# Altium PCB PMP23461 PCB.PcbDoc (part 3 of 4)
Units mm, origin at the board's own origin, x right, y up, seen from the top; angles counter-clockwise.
Board outline 240.04 x 159.92 mm, 6 copper layers (Layer 1, Layer 2, Layer 3, Layer 4, Layer 5, Layer 6), stack 2.017 mm thick; 241 components, 120 nets, 654 pads, 744 vias.
Unrouted connection lines stored in the file: 3.
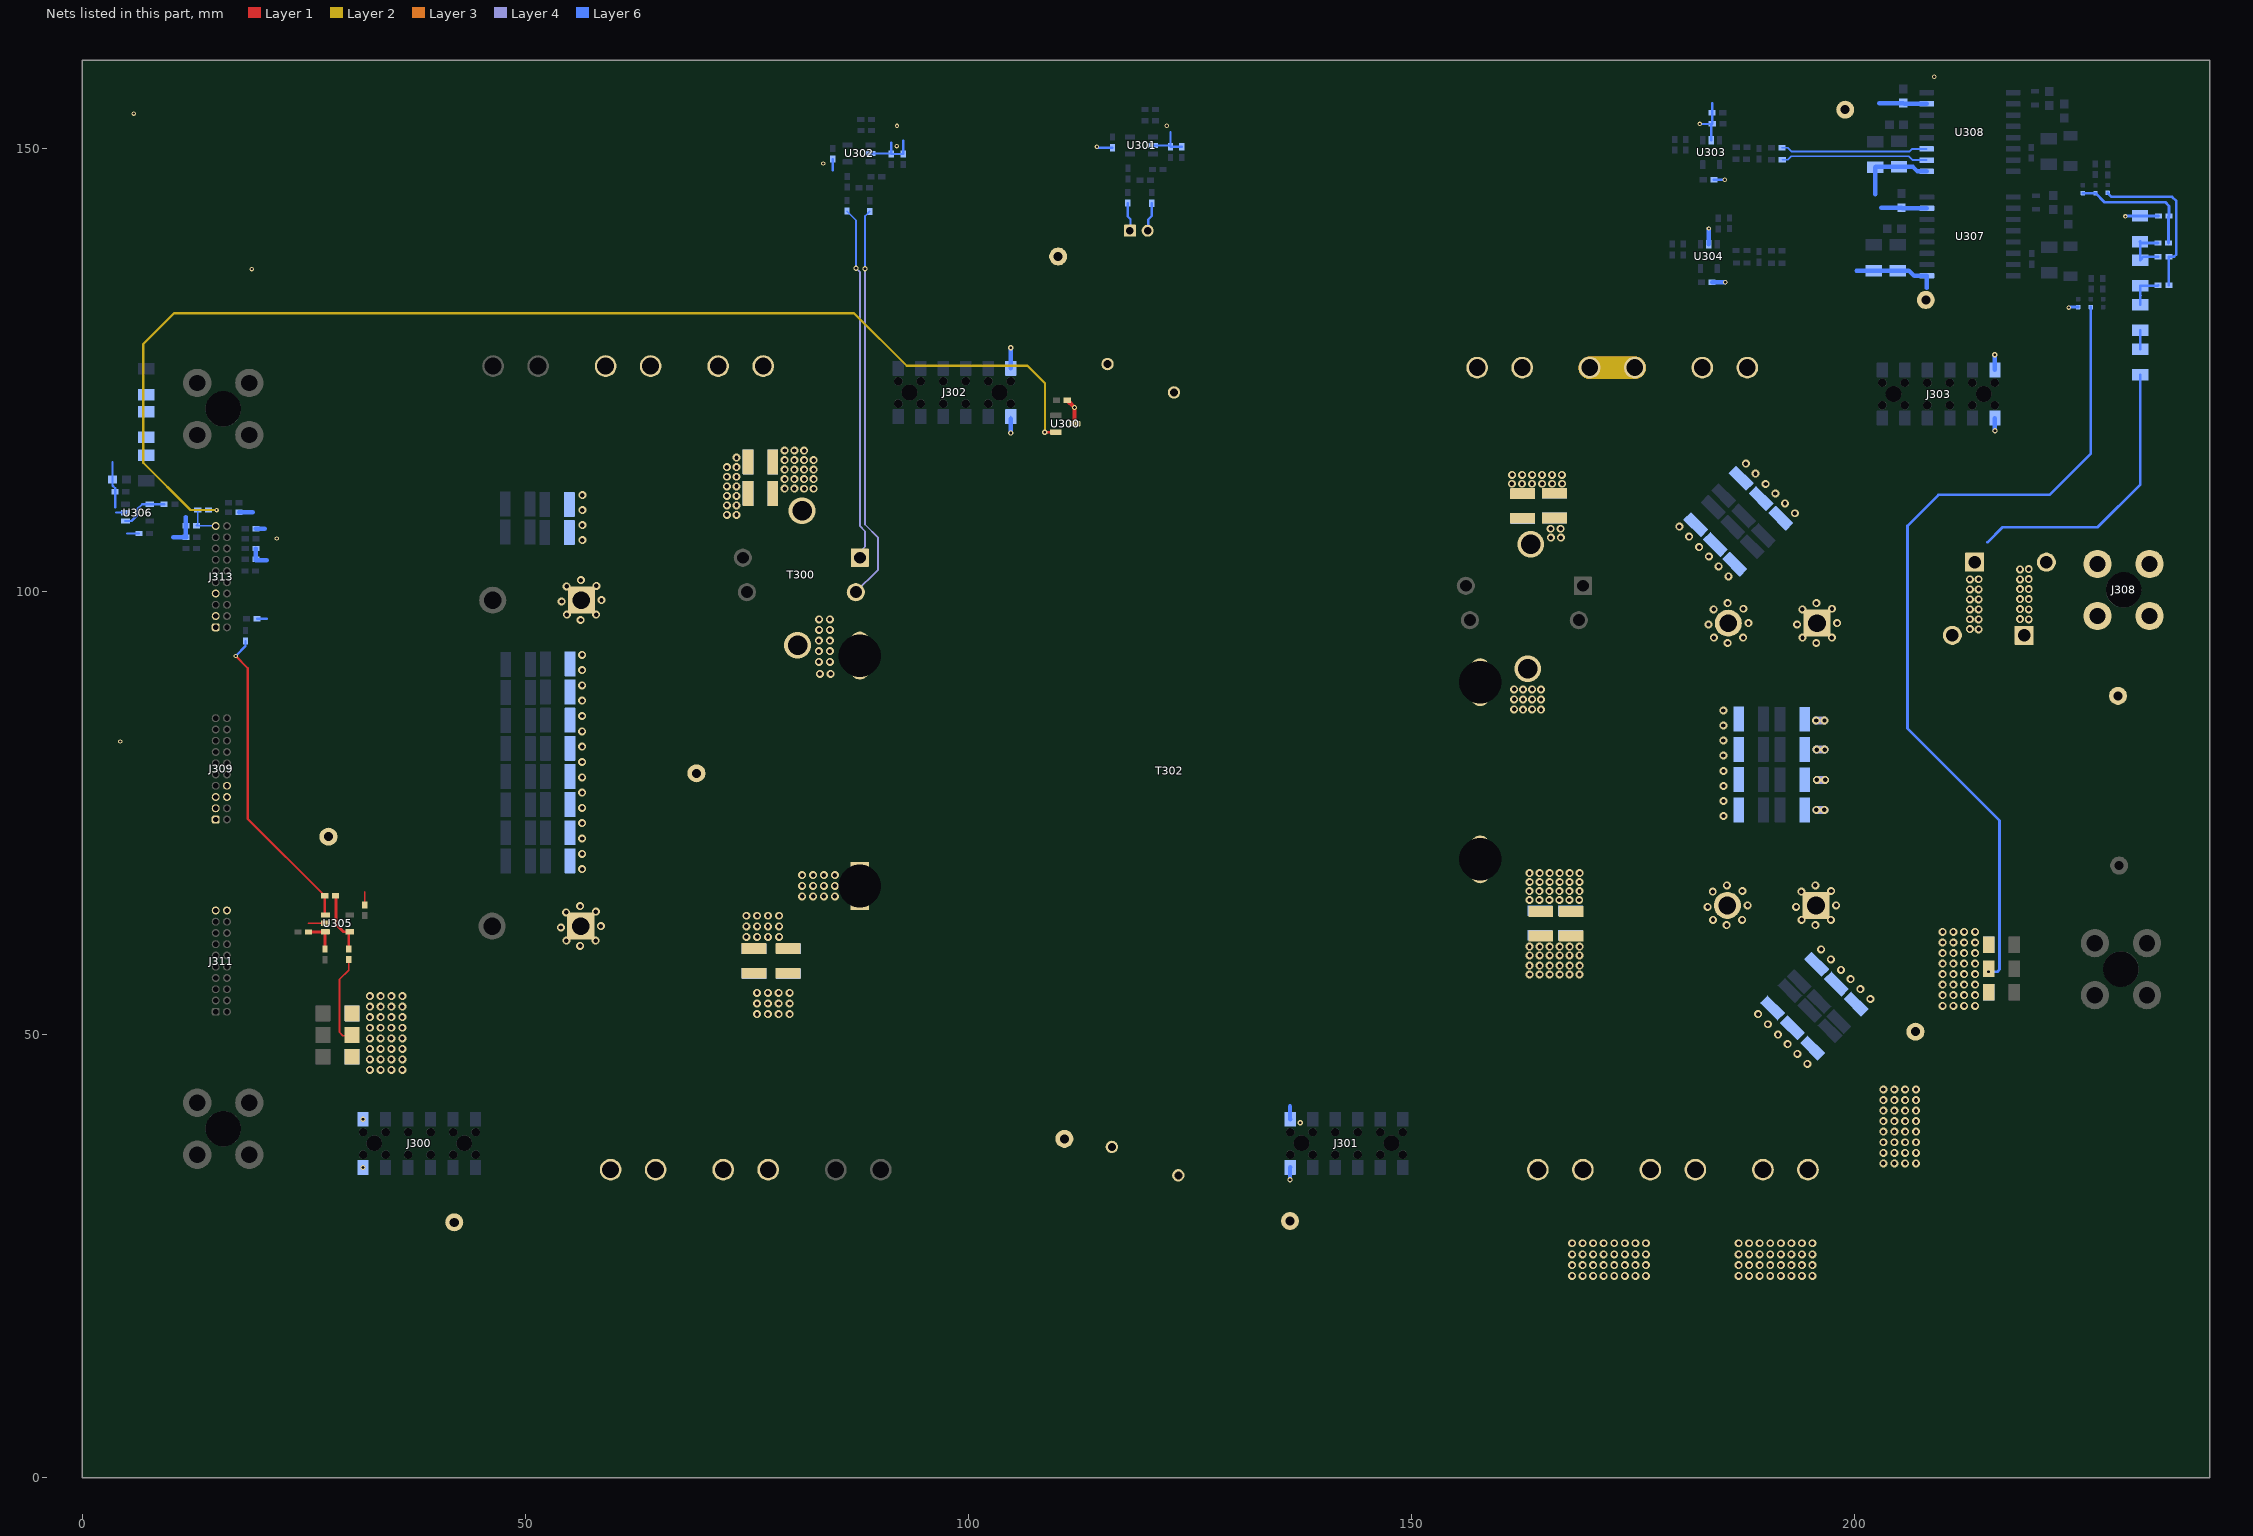
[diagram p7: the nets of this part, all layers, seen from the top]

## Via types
v1: diameter 0.9, hole 0.5, Layer 1 to Layer 6, 634 vias
v2: diameter 0.6, hole 0.3, Layer 1 to Layer 6, 52 vias
v3: diameter 0.5, hole 0.25, Layer 1 to Layer 6, 42 vias
v4: diameter 4, hole 4, Layer 1 to Layer 6, 12 vias
v5: diameter 3, hole 2.2, Layer 1 to Layer 6, 4 vias

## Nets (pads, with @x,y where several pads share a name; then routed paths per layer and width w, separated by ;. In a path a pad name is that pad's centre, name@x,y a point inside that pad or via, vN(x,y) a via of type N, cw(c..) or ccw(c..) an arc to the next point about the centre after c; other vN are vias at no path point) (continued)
NetR307_1: R307.1 U300.2 | length 138.1
  Layer 1 w0.254: v2(108.61,117.949) 108.622,117.961 U300.2@109.853,117.961
  Layer 2 w0.254: v3(15.137,109.177) 12.209,109.177 6.857,114.529 6.857,127.914 10.337,131.394 87.07,131.394 93.014,125.451 106.654,125.451 108.61,123.495 v2(108.61,117.949)
  Layer 6 w0.254: R307.1@14.213,109.195 14.231,109.177 v3(15.137,109.177)
NetR333_1: R333.1 R335.1 R340.1 R345.1 | length 6.4
  Layer 6 w0.305: R333.1@232.192,139.468 R333.1@232.224,139.437 ; R333.1@232.224,139.517 R333.1@232.224,139.437 ; R335.1@234.212,139.316 232.344,139.316 R333.1@232.224,139.437 ; R340.1@234.238,137.767 232.602,137.767 R345.1@232.224,137.388 R333.1@232.224,139.437
NetR336_2: R336.2 R356.1 U305.4 | length 7.1
  Layer 1 w0.305: R356.1@28.548,65.644 28.625,65.568 28.625,62.433 29.468,61.59 U305.4@30.168,61.59 30.056,61.479 R336.2@30.056,59.666
NetR342_2: R342.2 R348.1 U305.3 | length 3.8
  Layer 1 w0.305: R342.2@25.516,61.57 27.363,61.57 27.38,61.552 R348.1@27.38,59.63
NetR345_2: R345.2 R349.1 R351.1 | length 4.2
  Layer 6 w0.305: R351.1@232.224,132.359 232.224,133.374 ; 232.247,133.398 232.224,133.374 ; R349.1@234.238,134.541 234.185,134.488 R345.2@232.224,134.488 232.224,133.374
NetR346_1: R346.1 R356.2 U305.1 | length 35.5
  Layer 1 w0.254: v3(17.296,92.71) 18.668,91.338 18.668,74.324 R356.2@27.348,65.644 27.348,63.559 U305.1@27.418,63.49
  Layer 6 w0.254: v3(17.296,92.71) 18.414,93.828 R346.1@18.414,94.38
NetR347_1: R347.1 U306.1 U306.4 | length 5.6
  Layer 6 w0.254: U306.1@4.848,107.94 5.551,107.94 6.172,108.561 6.172,109.245 6.767,109.84 U306.4@7.598,109.84 9.22,109.84 R347.1@9.23,109.83
NetR350_1: R350.1 R352.2
NetR351_2: R351.2 R353.1 | length 2.1
  Layer 6 w0.305: R353.1@232.224,127.33 R351.2@232.224,129.459
NetR352_1: R352.1 R355.2
PGND: C300.2 C301.2 C318.2 C319.1 C320.1 C322.2 C324.2 C326.2 C327.2 C328.2 C330.2 C332.2 C333.2 C334.1 C335.2 C338.2 C339.2 C342.2 C344.2 C345.2 C346.2 C348.2 C349.2 C350.2 C354.2 C355.2 C357.2 C363.2 C364.2 C366.2 C369.2 C370.2 C371.2 C372.2 C373.2 C374.2 C375.2 C376.2 J300.11 J300.12 J301.11 J301.12 J302.11 J302.12 J303.11 J303.12 J309.1 J309.3 J309.5 J309.6 J309.8 J311.19 J311.20 J313.1 J313.3 R300.2 R302.2 R304.2 R306.2 R309.2 R311.1 R318.1 R319.1 R336.1 R339.2 TP300.1 TP302.1 TP312.1 TP314.1 TP327.1 TP328.1 TP329.1 TP330.1 TP331.1 TP332.1 TP333.1 TP334.1 U300.3 U301.2 U302.2 U303.2 U304.2 U305.2 U306.2 U307.9 U307.15 U308.9 U308.15 | length 97.9
  Layer 1 w0.2: 25.496,62.54 U305.2@27.418,62.54 ; R336.1@30.056,58.466 30.056,57.261 29.006,56.21 29.006,50.241 29.387,49.86 30.365,49.86 R304.2@30.443,49.938 ; C349.2@31.851,64.633 31.851,66.091
  Layer 1 w0.5: C322.2@111.13,121.578 v2(111.953,120.756) U300.3@111.953,118.911
  Layer 6 w0.2: J302.11@104.764,119.482 J302.11@104.764,119.73
  Layer 6 w0.254: 3.391,114.567 R339.2@3.391,112.624 3.391,111.951 3.693,111.649 C345.2@3.693,111.227 3.693,109.498 ; 3.785,108.89 U306.2@4.848,108.89 ; 5.055,106.528 C350.2@6.368,106.528 ; C344.2@19.716,96.926 20.799,96.926 ; 84.668,147.482 C338.2@84.668,148.8 ; U302.2@88.945,149.421 91.221,149.421 C335.2@91.277,149.366 ; 91.277,150.658 C335.2@91.277,149.366 ; 92.623,150.879 R319.1@92.623,149.361 92.618,149.366 C335.2@91.277,149.366 ; v3(114.477,150.165) 114.574,150.067 C330.2@116.236,150.067 ; U301.2@120.817,150.317 122.642,150.317 C327.2@122.789,150.17 ; 122.789,151.841 C327.2@122.789,150.17 ; R311.1@124.059,150.17 C327.2@122.789,150.17 ; v3(182.513,152.756) C334.1@183.889,152.756 ; U303.2@183.794,150.905 C334.1@183.794,152.66 ; 183.905,155.083 R318.1@183.905,154 183.905,152.772 C334.1@183.889,152.756 ; C334.1@183.921,152.756 C334.1@183.889,152.756 ; C339.2@184.099,146.457 v3(185.319,146.457)
  Layer 6 w0.5: 10.261,106.096 C328.2@11.702,106.096 ; 11.667,106.416 C318.2@11.667,107.417 11.667,108.391 ; C342.2@17.668,108.949 19.228,108.949 ; C332.2@19.573,104.838 19.573,103.53 19.547,103.505 20.802,103.505 ; C346.2@19.573,107.086 20.584,107.086 ; v2(104.764,117.881) J302.11@104.764,119.482 ; J302.12@104.764,125.17 104.774,125.18 v2(104.774,127.508) ; v2(136.27,33.604) 136.27,34.973 J301.12@136.293,34.996 ; 136.27,41.885 136.27,40.459 J301.11@136.293,40.436 ; U304.2@183.538,139.167 v3(183.538,140.947) ; C348.2@183.901,134.896 v3(185.392,134.896) ; 200.198,136.19 C354.2@202.148,136.19 202.162,136.204 C355.2@204.864,136.204 206.098,136.204 206.694,135.608 U307.9@208.144,135.608 208.144,134.239 ; 202.3,144.816 C363.2@202.3,147.848 202.352,147.9 C364.2@204.991,147.9 206.569,147.9 207.075,147.393 U308.9@208.119,147.393 ; 202.758,155.102 C366.2@205.475,155.102 205.564,155.013 U308.15@208.119,155.013 ; 203.011,143.292 C357.2@205.271,143.292 205.335,143.228 U307.15@208.144,143.228 ; v2(215.797,126.705) 215.813,126.689 J303.12@215.813,124.993 ; J303.11@215.813,119.553 215.813,118.12 v2(215.823,118.11)
  other v1: 32.43,45.999 33.65,45.999 34.869,45.999 36.113,45.999 32.43,47.19 33.65,47.19 34.869,47.19 36.113,47.19 32.43,48.38 33.65,48.38 34.869,48.38 36.113,48.38 32.43,49.57 33.65,49.57 34.869,49.57 36.113,49.57 32.43,50.76 33.65,50.76 34.869,50.76 36.113,50.76 32.43,51.95 33.65,51.95 34.869,51.95 36.113,51.95 32.43,53.14 33.65,53.14 34.869,53.14 36.113,53.14 32.43,54.331 33.65,54.331 34.869,54.331 36.113,54.331 56.161,59.992 54.612,60.601 57.914,60.601 54.002,62.075 58.512,62.227 54.586,63.776 57.939,63.853 56.169,64.488 56.387,68.656 56.387,70.384 56.387,72.112 56.387,73.84 56.387,75.568 56.387,77.296 56.387,79.024 56.387,80.752 56.387,82.48 56.387,84.207 56.387,85.935 56.387,87.663 56.387,89.391 56.387,91.119 56.387,92.847 56.228,96.774 54.679,97.384 57.981,97.384 54.069,98.857 58.579,99.009 54.653,100.559 58.006,100.635 56.236,101.27 56.412,105.791 56.412,107.484 56.412,109.178 56.412,110.871
  other v2: 31.671,34.996 137.414,40.056 31.671,40.436
  other v3: 4.266,83.058 21.919,105.969 19.1,136.373 83.591,148.285 91.896,150.254 91.923,152.527 122.351,152.552 5.79,153.918 208.966,158.064
ROG_PRI_N: R322.1 T300.2 | length 45
  Layer 4 w0.2: T300.2@87.173,99.835 89.788,102.45 89.788,106.07 88.313,107.546 v2(88.313,136.423)
  Layer 6 w0.2: v2(88.313,136.423) 88.313,142.352 R322.1@88.838,142.878
ROG_PRI_P: R327.1 T300.1 | length 40.3
  Layer 4 w0.203: v2(87.299,136.449) 87.756,135.992 87.756,107.35 88.313,106.793 88.313,105.029 87.63,104.346 T300.1@87.63,103.721
  Layer 6 w0.203: R327.1@86.281,142.906 87.299,141.887 v2(87.299,136.449)
ROG_SEC_N: J304.2 R312.1 | length 3
  Layer 6 w0.254: J304.2@120.272,140.941 120.272,141.959 120.681,142.367 R312.1@120.681,143.796
ROG_SEC_P: J304.1 R314.1 | length 3
  Layer 6 w0.254: R314.1@117.963,143.807 117.963,142.313 118.272,142.003 J304.1@118.272,140.941
SGND: C300.1 C301.1 C323.1 C325.1 C377.2 C378.2 C379.2 C380.2 C381.2 C382.2 C383.2 C384.2 C385.2 C386.2 FB300.1 FB301.1 R301.1 R303.1 R305.1 R308.1 R310.1 R332.1 R333.2 TP301.1 TP303.1 TP313.1 TP315.1 TP324.1 | length 104.8
  Layer 4 w0.9: v1(195.642,85.432) v1@196.531,85.432 ; v1(195.655,75.345) v1(196.57,75.345) ; v1(195.696,82.144) v1(196.61,82.144) ; v1(195.731,78.74) v1(196.646,78.74)
  Layer 6 w0.305: v2(215.086,57.074) 216.077,57.074 216.331,57.328 216.331,74.143 205.943,84.53 205.943,107.391 209.448,110.896 221.996,110.896 226.618,115.518 226.618,132.069 FB301.1@226.633,132.084 ; v3(224.154,132.029) 224.209,132.084 FB300.1@225.211,132.084 ; v3(230.545,142.313) 230.6,142.368 R333.2@232.192,142.368 232.196,142.364 R332.1@234.263,142.364
  other v1: 168.097,22.758 169.287,22.758 170.478,22.758 171.668,22.758 172.858,22.758 174.048,22.758 175.238,22.758 176.428,22.758 186.893,22.758 188.083,22.758 189.274,22.758 190.464,22.758 191.654,22.758 192.844,22.758 194.034,22.758 195.224,22.758 168.097,23.978 169.287,23.978 170.478,23.978 171.668,23.978 172.858,23.978 174.048,23.978 175.238,23.978 176.428,23.978 186.893,23.978 188.083,23.978 189.274,23.978 190.464,23.978 191.654,23.978 192.844,23.978 194.034,23.978 195.224,23.978 168.097,25.197 169.287,25.197 170.478,25.197 171.668,25.197 172.858,25.197 174.048,25.197 175.238,25.197 176.428,25.197 186.893,25.197 188.083,25.197 189.274,25.197 190.464,25.197 191.654,25.197 192.844,25.197 194.034,25.197 195.224,25.197 168.097,26.441 169.287,26.441 170.478,26.441 171.668,26.441 172.858,26.441 174.048,26.441 175.238,26.441 176.428,26.441 186.893,26.441 188.083,26.441 189.274,26.441 190.464,26.441 191.654,26.441 192.844,26.441 194.034,26.441 195.224,26.441 203.225,35.458 204.47,35.458 205.689,35.458 206.908,35.458 203.225,36.649 204.47,36.649 205.689,36.649 206.908,36.649 203.225,37.839 204.47,37.839 205.689,37.839 206.908,37.839 203.225,39.029 204.47,39.029 205.689,39.029 206.908,39.029 203.225,40.219 204.47,40.219 205.689,40.219 206.908,40.219 203.225,41.409 204.47,41.409 205.689,41.409 206.908,41.409 203.225,42.599 204.47,42.599 205.689,42.599 206.908,42.599 203.225,43.79 204.47,43.79 205.689,43.79 206.908,43.79 209.905,53.238 211.124,53.238 212.343,53.238 213.588,53.238 201.751,54.006 209.905,54.429 211.124,54.429 212.343,54.429 213.588,54.429 200.634,55.118 209.905,55.619 211.124,55.619 212.343,55.619 213.588,55.619 199.541,56.236 209.905,56.809 211.124,56.809 212.343,56.809 213.588,56.809 198.449,57.302 209.905,57.999 211.124,57.999 212.343,57.999 213.588,57.999 197.306,58.471 209.905,59.189 211.124,59.189 212.343,59.189 213.588,59.189 196.214,59.614 209.905,60.379 211.124,60.379 212.343,60.379 213.588,60.379 209.905,61.57 211.124,61.57 212.343,61.57 213.588,61.57 195.549,62.329 193.999,62.938 197.301,62.938 193.39,64.411 197.9,64.564 193.974,66.113 197.327,66.189 195.557,66.824 196.581,85.432 195.654,94.18 194.105,94.79 197.407,94.79 193.495,96.263 198.005,96.415 194.079,97.965 197.432,98.041 195.662,98.676 193.242,108.819 192.125,109.931 191.032,111.049 189.94,112.116 188.797,113.284 187.705,114.427
SW_A: C310.2 C312.2 C314.2 C316.2 TP316.1 TP318.1
  other v1: 72.719,108.636 73.811,108.636 72.719,109.711 73.811,109.711 72.719,110.786 73.811,110.786 72.719,111.862 73.811,111.862 72.719,112.937 73.811,112.937 72.719,114.012 73.811,114.012 73.811,115.087
SW_A_RES: C310.1 C312.1 C314.1 C316.1
  other v1: 81.432,111.582 82.525,111.582 79.237,111.596 80.329,111.596 81.432,112.657 82.525,112.657 79.237,112.671 80.329,112.671 79.237,113.747 80.329,113.747 81.432,113.732 82.525,113.732 81.432,114.807 82.525,114.807 79.237,114.822 80.329,114.822 81.432,115.883 79.237,115.897 80.329,115.897
  other v5: 81.204,109.093
SW_A_XFMR: T302.2
  other v1: 83.21,90.7 84.43,90.7 83.108,92.057 84.352,92.057 83.108,93.247 84.352,93.247 83.108,94.437 84.352,94.437 83.134,95.66 84.353,95.66 83.134,96.85 84.353,96.85
  other v5: 80.696,93.929
SW_B: C302.2 C304.2 C306.2 C308.2 TP304.1 TP306.1
  other v1: 76.123,52.306 77.342,52.306 78.561,52.306 79.806,52.306 76.123,53.496 77.342,53.496 78.561,53.496 79.806,53.496 76.123,54.686 77.342,54.686 78.561,54.686 79.806,54.686
SW_B_RES: C302.1 C304.1 C306.1 C308.1 T302.1
  other v1: 74.929,61.018 76.148,61.018 77.367,61.018 78.612,61.018 74.929,62.208 76.148,62.208 77.367,62.208 78.612,62.208 74.929,63.398 76.148,63.398 77.367,63.398 78.612,63.398 81.228,65.59 82.447,65.59 83.667,65.59 84.911,65.59 81.228,66.78 82.447,66.78 83.667,66.78 84.911,66.78 81.228,67.97 82.447,67.97 83.667,67.97 84.911,67.97
SW_C: C311.2 C313.2 C315.2 C317.2 TP317.1 TP319.1 | length 15.2
  Layer 3 w2.54: TP317.1@170.093,125.244 TP319.1@175.173,125.244
  Layer 4 w2.54: TP317.1@170.093,125.244 TP319.1@175.173,125.244
  Layer 2 w2.54: TP317.1@170.093,125.244 TP319.1@175.173,125.244
  other v1: 161.314,112.148 162.447,112.148 163.58,112.148 164.713,112.148 165.846,112.148 166.979,112.148 161.34,113.138 162.462,113.138 163.585,113.138 164.708,113.138 165.831,113.138 166.953,113.138
SW_C_RES: C311.1 C313.1 C315.1 C317.1
  other v1: 165.698,106.077 166.831,106.077 165.683,107.068 166.806,107.068
  other v5: 163.424,105.308
SW_C_XFMR: T302.3
  other v1: 162.559,86.665 164.591,86.665 161.568,86.69 163.6,86.69 161.568,87.813 162.559,87.798 163.6,87.813 164.591,87.798 162.559,88.93 164.591,88.93 161.568,88.936 163.6,88.936
  other v5: 163.093,91.262
SW_D: C303.1 C305.1 C307.1 C309.1 TP305.1 TP307.1
  other v1: 163.321,56.769 164.444,56.769 165.566,56.769 166.689,56.769 167.812,56.769 168.934,56.769 163.296,57.76 164.428,57.76 165.561,57.76 166.694,57.76 167.827,57.76 168.96,57.76 163.321,58.928 164.444,58.928 165.566,58.928 166.689,58.928 167.812,58.928 168.934,58.928 163.296,59.919 164.428,59.919 165.561,59.919 166.694,59.919 167.827,59.919 168.96,59.919
SW_D_RES: C303.2 C305.2 C307.2 C309.2 T302.4
  other v1: 163.296,65.176 164.418,65.176 165.541,65.176 166.664,65.176 167.786,65.176 168.909,65.176 163.27,66.167 164.403,66.167 165.536,66.167 166.669,66.167 167.802,66.167 168.934,66.167 163.321,67.208 164.444,67.208 165.566,67.208 166.689,67.208 167.812,67.208 168.934,67.208 163.296,68.199 164.428,68.199 165.561,68.199 166.694,68.199 167.827,68.199 168.96,68.199
SYSTEM_TEMP_1: C318.1 J313.19 R307.2 | length 4
  Layer 6 w0.203: R307.2@13.013,109.195 13.013,107.563 C318.1@12.867,107.417 15.004,107.417 J313.19@15.042,107.378
VBATT: F300.1 F301.2 J308.1 TP326.1
  other v1: 219.634,96.85 218.643,96.876 218.643,97.998 219.634,97.983 219.634,99.116 218.643,99.121 218.643,100.244 219.634,100.249 218.643,101.366 219.634,101.382 218.643,102.489 219.634,102.514
VBATT_F: C323.2 C325.2 C397.1 C398.1 C399.1 C400.1 C401.1 C402.1 C403.1 C404.1 C405.1 C406.1 F300.2 F301.1 R353.2 TP309.1 TP311.1 TP321.1 TP323.1 | length 32.3
  Layer 6 w0.305: 214.986,105.537 216.687,107.239 227.406,107.239 232.221,112.054 232.221,124.427 R353.2@232.224,124.43
  other v1: 194.639,46.691 193.522,47.803 192.429,48.92 191.337,49.987 190.194,51.156 189.102,52.299 185.549,62.329 183.999,62.938 187.301,62.938 183.39,64.411 187.9,64.564 183.974,66.113 187.327,66.189 185.557,66.824 185.19,74.651 185.19,76.344 185.19,78.037 185.19,79.731 185.165,81.48 185.165,83.174 185.165,84.867 185.165,86.56 185.654,94.18 184.105,94.79 187.407,94.79 213.969,95.707 212.978,95.733 183.495,96.263 188.005,96.415 212.978,96.855 213.969,96.84 184.079,97.965 213.969,97.973 212.978,97.978 187.432,98.041 185.662,98.676 212.978,99.101 213.969,99.106 212.978,100.223 213.969,100.239 212.978,101.346 213.969,101.371 185.749,101.707 184.632,102.819 183.539,103.937 182.447,105.004 181.304,106.172 180.212,107.315
VSNS_INN: FB303.1 FB304.1 R332.2 R335.2 | length 14.5
  Layer 6 w0.305: FB303.1@225.744,144.937 FB304.1@227.167,144.937 228.19,143.914 235.041,143.914 235.463,143.491 R332.2@235.463,142.364 235.412,142.313 R335.2@235.412,139.316
VSNS_INP: FB305.1 R340.2 R349.2 | length 18.3
  Layer 6 w0.305: FB305.1@228.538,144.962 228.977,144.523 235.803,144.523 236.285,144.041 236.285,138.03 236.022,137.767 R340.2@235.438,137.767 R349.2@235.438,134.541
VSNS_OUTN: R325.1 U308.10 | length 16.6
  Layer 6 w0.203: R325.1@191.82,148.717 192.455,148.717 192.836,149.098 206.107,149.098 206.542,148.663 U308.10@208.119,148.663
VSNS_OUTP: R320.1 U308.11 | length 16.6
  Layer 6 w0.203: R320.1@191.785,150.063 192.455,150.063 192.887,149.632 206.164,149.632 206.466,149.933 U308.11@208.119,149.933
XRSn: J313.7
pads on no net: J300. J301. J302. J303. J305. J306. J307. J308. T300.3 T300.4 T301.1 T301.2 T301.3 T301.4 U307.4 U308.4
copper on no net:
  other v4: 14,6 82.245,6 153.746,6 234.041,6 6,20 80.017,79.407 157.314,79.407 6,140 14,153.918 76.017,153.918 153.314,153.918 234.041,153.918

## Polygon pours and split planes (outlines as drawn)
DCLINK on Layer 6 "LAYER_6_DCLINK_P1123" (solid, remove dead copper, pour order 1123): 83.871,33.274 83.083,34.061 83.083,37.414 84.125,38.456 92.253,38.456 93.015,37.694 93.015,34.163 92.126,33.274
PGND on Layer 6 "LAYER_6_PGND_P1093" (solid, remove dead copper, pour order 1093): 94 vertices, not listed, extent 1.371,14.503 210.057,158.953
DCLINK on Layer 6 "LAYER_6_DCLINK_P1065" (solid, remove dead copper, pour order 1065): 24 vertices, not listed, extent 6.274,59.652 42.367,125.806
SW_C_RES on Layer 6 "NONET_L-01_P-001" (solid, remove dead copper, pour order 1053): 167.263,103.505 168.477,104.72 168.477,108.515 168.02,108.973 166.274,108.973 161.314,108.973 160.883,108.541 160.883,104.82 162.197,103.505
SW_C on Layer 6 "NONET_L-01_P-001" (solid, remove dead copper, pour order 1051): 160.781,114.275 160.781,114.757 163.773,117.75 167.537,121.514 167.537,125.991 168.496,126.949 176.454,126.949 177.51,125.893 177.51,119.04 168.782,110.312 161.138,110.312 160.781,110.669
NetC324_1 on Layer 6 "LAYER_6_NETC324_1_P911" (solid, remove dead copper, pour order 911): 49.935,93.116 50.139,93.32 52.729,93.32 52.882,93.167 52.882,68.174 52.806,68.097 49.986,68.097 49.91,68.174 49.91,68.25
NetC377_1 on Layer 6 "LAYER_6_NETC377_1_P899" (solid, remove dead copper, pour order 899): 191.251,55.471 191.251,55.666 192.986,57.401 193.182,57.401 199.633,50.95 199.633,50.797 197.855,49.019 197.703,49.019
NetC377_1 on Layer 6 "LAYER_6_NETC377_1_P897" (solid, remove dead copper, pour order 897): 189.016,86.56 189.016,86.992 189.245,87.221 192.039,87.221 192.216,87.043 192.216,73.937 192.115,73.835 189.168,73.835 189.067,73.937
NetC377_1 on Layer 6 "LAYER_6_NETC377_1_P895" (solid, remove dead copper, pour order 895): 182.42,110.233 184.452,112.265 184.723,112.265 184.723,112.126 191.023,105.827 191.023,105.61 189.118,103.705 188.864,103.705 182.42,110.149
DCLINK on Layer 6 "LAYER_6_DCLINK_P893" (solid, remove dead copper, pour order 893): 19 vertices, not listed, extent 38.242,58.188 53.405,128.013
IPRI_SENSE on Layer 6 "LAYER_6_IPRI_SENSE_P891" (solid, remove dead copper, pour order 891): 12.211,48.895 11.365,48.05 11.366,34.179 12.401,33.144 27.061,33.144 28.031,34.098 28.031,54.404 26.989,55.445 20.995,55.445 20.182,54.633 20.182,51.196 17.882,48.895
PGND on Layer 6 "LAYER_6_PGND_P889" (solid, remove dead copper, pour order 889): 29 vertices, not listed, extent 29.504,31.572 66.563,111.582
PGND on Layer 6 "LAYER_6_PGND_P863" (solid, remove dead copper, pour order 863): 70.737,128.286 77.842,128.286 78.595,127.534 78.595,124.475 77.739,123.619 70.906,123.619 70.06,124.465 70.06,127.609
PGND on Layer 6 "LAYER_6_PGND_P861" (solid, remove dead copper, pour order 861): 57.927,46.911 58.612,47.597 65.928,47.597 66.461,47.063 66.461,33.677 65.674,32.89 58.765,32.89 57.927,33.728
SW_C_XFMR on Layer 6 "NONET_L-01_P-001" (solid, remove dead copper, pour order 845): 154.955,87.146 156.216,85.951 165.851,85.951 166.994,87.094 166.994,92.848 165.405,94.437 157.371,94.437 154.955,92.021
SW_D on Layer 6 "NONET_L-01_P-001" (solid, remove dead copper, pour order 841): 169.941,61.719 170.601,61.059 170.601,60.284 170.601,57.503 184.342,43.761 184.342,32.89 183.453,32.001 175.402,32.001 174.538,32.865 174.538,39.265 161.355,52.448 161.355,55.741 161.355,61.099 162.008,61.719
SW_D_RES on Layer 6 "NONET_L-01_P-001" (solid, remove dead copper, pour order 839): 155.056,64.691 156.428,63.319 170.169,63.319 170.703,63.853 170.703,72.463 169.458,73.708 156.199,73.708 155.056,72.51
VBATT_F on Layer 6 "LAYER_6_VBATT_F_P837" (solid, remove dead copper, pour order 837): 17 vertices, not listed, extent 175.554,32.103 197.754,108.912
SGND on Layer 6 "LAYER_6_SGND_P835" (solid, remove dead copper, pour order 835): 20 vertices, not listed, extent 180.609,48.46 215.772,126.949
VBATT on Layer 6 "LAYER_6_VBATT_P833" (solid, remove dead copper, pour order 833): 218.719,106.426 217.058,104.764 217.058,91.716 223.128,85.646 235.904,85.646 237.352,87.094 237.352,104.837 235.763,106.426
VBATT_F on Layer 6 "LAYER_6_VBATT_F_P831" (solid, remove dead copper, pour order 831): 209.728,105.795 209.728,93.599 210.617,92.71 215.417,92.71 216.346,93.639 216.346,105.624 214.935,107.036 210.803,107.036
BATT_RTN on Layer 6 "LAYER_6_BATT_RTN_P829" (solid, remove dead copper, pour order 829): 217.972,48.409 217.413,48.968 217.413,69.72 218.632,70.939 238.444,70.939 239.384,69.999 239.384,49.425 238.368,48.409
VBATT_F on Layer 6 "LAYER_6_VBATT_F_P827" (solid, remove dead copper, pour order 827): 156.82,127.025 163.195,127.025 164.243,125.977 164.243,123.281 163.057,122.095 157.063,122.095 155.709,123.449 155.709,125.915
SGND on Layer 6 "LAYER_6_SGND_P825" (solid, remove dead copper, pour order 825): 162.305,20.93 166.979,16.256 211.022,16.256 215.772,21.006 215.772,53.01 201.523,53.01 201.523,31.775 198.5,28.753 172.821,28.753 171.083,30.49 171.083,33.144 171.083,37.208 170.042,38.249 163.286,38.249 162.305,37.269
SW_B on Layer 6 "LAYER_6_SW_B_P625" (solid, remove dead copper, pour order 625): 70.684,46.968 70.627,47.025 70.627,55.108 73.075,57.556 81.991,57.556 82.677,56.871 82.677,50.598 79.161,47.082 79.161,33.677 78.374,32.89 71.465,32.89 70.627,33.728 70.627,46.911
SW_B_RES on Layer 6 "LAYER_6_SW_B_RES_P623" (solid, remove dead copper, pour order 623): 73.766,58.466 73.1,59.131 73.1,63.373 79.752,70.025 88.711,70.025 89.321,69.415 89.321,63.693 84.093,58.466
SW_A on Layer 6 "LAYER_6_SW_A_P567" (solid, remove dead copper, pour order 567): 73.341,116.586 75.489,116.586 76.148,115.927 76.148,108.838 75.159,107.848 69.963,107.848 56.987,120.825 56.987,126.768 57.825,127.607 65.343,127.607 65.928,127.022 65.928,124
SW_A_RES on Layer 6 "LAYER_6_SW_A_RES_P543" (solid, remove dead copper, pour order 543): 76.961,106.554 77.737,105.778 82.029,105.778 83.073,106.822 83.073,115.883 82.395,116.561 77.445,116.561 76.961,116.077
SW_A_XFMR on Layer 6 "NONET_L-01_P-001" (solid, remove dead copper, pour order 523): 88.051,96.136 85.715,96.136 82.484,99.413 78.341,99.413 77.231,98.323 77.231,90.7 78.12,89.811 83.165,89.811 88.5,89.811 89.194,90.541 89.194,94.993
DCLINK on Layer 1 "LAYER_1_DCLINK_P1013" (solid, remove dead copper, pour order 1013): 82.91,36.012 83.799,36.901 90.911,36.901 91.445,36.368 91.445,33.169 90.886,32.61 83.647,32.61 82.911,33.346
SGND on Layer 1 "LAYER_1_SGND_P975" (solid, remove dead copper, pour order 975): 18 vertices, not listed, extent 162.549,16.307 215.772,52.502
PGND on Layer 1 "LAYER_1_PGND_P917" (solid, remove dead copper, pour order 917): 85 vertices, not listed, extent 1.219,14.529 209.549,159.258
PGND on Layer 1 "LAYER_1_PGND_P865" (solid, remove dead copper, pour order 865): 25 vertices, not listed, extent 29.504,32.588 66.563,111.582
SGND on Layer 1 "LAYER_1_SGND_P651" (solid, remove dead copper, pour order 651): 162.549,37.513 163.286,38.249 170.042,38.249 171.083,37.208 171.083,33.144 170.525,32.585 163.286,32.585 162.549,33.322
VBATT_F on Layer 1 "LAYER_1_VBATT_F_P649" (solid, remove dead copper, pour order 649): 156.388,127.483 163.373,127.483 164.243,126.612 164.243,123.281 163.057,122.095 157.063,122.095 155.709,123.449 155.709,126.804
PGND on Layer 1 "LAYER_1_PGND_P647" (solid, remove dead copper, pour order 647): 70.06,126.67 70.949,127.559 78.061,127.559 78.595,127.025 78.595,123.826 78.036,123.268 70.797,123.268 70.06,124.004
BATT_RTN on Layer 1 "LAYER_1_BATT_RTN_P643" (solid, remove dead copper, pour order 643): 217.972,48.409 217.032,49.349 217.032,69.339 218.632,70.939 238.444,70.939 239.384,69.999 239.384,49.425 238.368,48.409
VBATT_F on Layer 1 "LAYER_1_VBATT_F_P641" (solid, remove dead copper, pour order 641): 209.488,106.632 209.488,93.342 210.555,92.275 215.254,92.275 216.346,93.367 216.346,106.652 215.356,107.642 210.364,107.642
VBATT on Layer 1 "LAYER_1_VBATT_P639" (solid, remove dead copper, pour order 639): 218.234,107.464 217.399,106.629 217.399,91.375 223.128,85.646 239.003,85.646 239.333,85.976 239.333,106.093 237.962,107.464
SGND on Layer 1 "LAYER_1_SGND_P637" (solid, remove dead copper, pour order 637): 206.11,106.208 191.962,120.356 191.962,126.362 191.073,127.302 181.117,127.302 180.609,126.794 180.609,117.294 185.562,112.341 191.962,105.94 191.962,59.535 203.037,48.46 215,48.46 215.813,49.273 215.813,76.362 206.11,86.065
VBATT_F on Layer 1 "LAYER_1_VBATT_F_P635" (solid, remove dead copper, pour order 635): 186.578,104.823 182.553,108.839 179.856,108.839 175.554,104.537 175.554,102.69 175.554,57.706 187.263,45.996 187.263,33.068 188.229,32.103 196.788,32.103 197.754,33.068 197.754,49.171 189.219,57.706 189.219,102.181
IPRI_SENSE on Layer 1 "LAYER_1_IPRI_SENSE_P631" (solid, remove dead copper, pour order 631): 12.325,48.92 17.652,48.92 19.735,51.003 19.735,54.635 20.545,55.445 26.989,55.445 28.031,54.404 28.031,34.313 26.862,33.144 12.689,33.144 11.099,34.735 11.099,47.715
SW_B_RES on Layer 1 "LAYER_1_SW_B_RES_P573" (solid, remove dead copper, pour order 573): 73.113,59.118 73.113,63.335 79.803,70.025 88.711,70.025 89.321,69.415 89.321,63.592 84.2,58.471 73.761,58.471
SW_B on Layer 1 "LAYER_1_SW_B_P571" (solid, remove dead copper, pour order 571): 70.627,46.911 70.627,55.108 73.075,57.556 81.991,57.556 82.677,56.871 82.677,50.579 79.161,47.063 79.161,33.144 78.602,32.585 71.363,32.585 70.627,33.322
DCLINK on Layer 1 "LAYER_1_DCLINK_P569" (solid, remove dead copper, pour order 569): 36 vertices, not listed, extent 10.719,58.188 53.405,128.013
SW_A on Layer 1 "LAYER_1_SW_A_P545" (solid, remove dead copper, pour order 545): 76.148,113.779 76.148,115.85 75.387,116.611 73.316,116.611 65.928,124 65.928,127.022 65.343,127.607 57.825,127.607 56.987,126.768 56.987,120.825 69.963,107.848 75.159,107.848 76.148,108.838
SW_A_RES on Layer 1 "LAYER_1_SW_A_RES_P525" (solid, remove dead copper, pour order 525): 76.936,116.069 77.428,116.561 82.395,116.561 83.073,115.897 83.073,106.822 81.966,105.715 77.775,105.715 76.936,106.554
SW_D_RES on Layer 1 "NONET_L-01_P-001" (solid, remove dead copper, pour order 70): 155.056,64.691 156.428,63.319 170.169,63.319 170.703,63.853 170.703,72.463 169.458,73.708 156.199,73.708 155.056,72.51
SW_D on Layer 1 "NONET_L-01_P-001" (solid, remove dead copper, pour order 80): 169.941,61.719 170.601,61.059 170.601,60.284 170.601,57.503 184.342,43.761 184.342,32.89 183.453,32.001 175.402,32.001 174.538,32.865 174.538,39.265 161.355,52.448 161.355,55.741 161.355,61.099 162.008,61.719
SW_C on Layer 1 "NONET_L-01_P-001" (solid, remove dead copper, pour order 81): 160.781,114.275 160.781,114.757 163.773,117.75 167.537,121.514 167.537,125.991 169.001,127.454 176.9,127.454 177.51,126.845 177.51,119.04 168.858,110.388 161.074,110.388 160.781,110.682
SW_C_XFMR on Layer 1 "NONET_L-01_P-001" (solid, remove dead copper, pour order 82): 154.955,87.146 156.216,85.951 165.851,85.951 166.994,87.094 166.994,92.772 165.303,94.463 157.396,94.463 154.955,92.021
SW_A_XFMR on Layer 1 "NONET_L-01_P-001" (solid, remove dead copper, pour order 113): 88.051,96.136 85.715,96.136 82.484,99.413 78.341,99.413 77.231,98.323 77.231,90.7 78.12,89.811 83.165,89.811 88.5,89.811 89.194,90.541 89.194,94.993
SW_C_RES on Layer 1 "NONET_L-01_P-001" (solid, remove dead copper, pour order 424): 167.263,103.505 168.477,104.72 168.477,108.515 168.02,108.973 166.274,108.973 161.314,108.973 160.883,108.541 160.883,104.82 162.197,103.505
SGND on Layer 3 "LAYER_3_SGND_P1117" (solid, remove dead copper, pour order 1117): 31 vertices, not listed, extent 119.141,0.889 239.13,132.483
SW_D on Layer 3 "NONET_L-01_P-001" (solid, remove dead copper, pour order 1115): 183.439,36.601 184.342,35.698 184.342,35.059 184.342,33.517 183.49,32.664 175.463,32.664 174.538,33.59 174.538,35.763 175.376,36.601
SW_D on Layer 3 "LAYER_3_SW_D_P1113" (solid, remove dead copper, pour order 1113): 162.027,51.816 167.776,46.076 181.407,46.076 181.407,46.66 170.612,57.455 170.612,61.087 170.005,61.694 161.998,61.694 161.314,61.01 161.314,52.528
VBATT_F on Layer 3 "LAYER_3_VBATT_F_P1111" (solid, remove dead copper, pour order 1111): 188.341,32.69 187.579,33.452 187.579,35.992 188.163,36.576 196.377,36.576 196.85,36.103 196.85,33.37 196.17,32.69
SGND on Layer 3 "LAYER_3_SGND_P1071" (solid, remove dead copper, pour order 1071): 17 vertices, not listed, extent 205.003,108.991 239.141,158.801
PGND on Layer 3 "LAYER_3_PGND_P1063" (solid, remove dead copper, pour order 1063): 0.965,128.83 0.965,155.703 4.292,159.029 31.165,159.029
PGND on Layer 3 "LAYER_3_PGND_P1045" (solid, remove dead copper, pour order 1045): 70.06,126.67 70.949,127.559 78.061,127.559 78.595,127.025 78.595,123.826 78.036,123.268 70.797,123.268 70.06,124.004
PGND on Layer 3 "LAYER_3_PGND_P1043" (solid, remove dead copper, pour order 1043): 25 vertices, not listed, extent 29.504,32.588 66.563,111.224
SW_B on Layer 3 "LAYER_3_SW_B_P1029" (solid, remove dead copper, pour order 1029): 70.627,46.911 70.627,55.108 73.075,57.556 83.108,57.556 83.844,56.82 83.844,51.747 79.161,47.063 79.161,33.144 78.602,32.585 71.363,32.585 70.627,33.322
SW_B_RES on Layer 3 "LAYER_3_SW_B_RES_P1027" (solid, remove dead copper, pour order 1027): 73.113,59.118 73.113,63.335 79.803,70.025 88.711,70.025 89.321,69.415 89.321,63.592 84.2,58.471 73.761,58.471
SW_A_RES on Layer 3 "LAYER_3_SW_A_RES_P993" (solid, remove dead copper, pour order 993): 76.936,106.783 78.321,105.398 81.269,105.398 83.073,107.201 83.073,115.964 82.425,116.611 77.275,116.611 76.936,116.272
SW_A on Layer 3 "LAYER_3_SW_A_P991" (solid, remove dead copper, pour order 991): 76.148,113.779 76.148,116.028 75.59,116.586 73.341,116.586 65.928,124 65.928,127.022 65.343,127.607 57.825,127.607 56.987,126.768 56.987,120.825 69.989,107.823 75.348,107.823 76.148,108.623
VBATT_F on Layer 3 "LAYER_3_VBATT_F_P965" (solid, remove dead copper, pour order 965): 44 vertices, not listed, extent 155.709,45.908 216.382,128.106
3V3_PRI on Layer 3 "LAYER_3_3V3_PRI_P925" (solid, remove dead copper, pour order 925): 2.59,73.965 14.502,73.965 14.934,74.397 14.934,75.692 16.28,77.038 28.485,77.038 29.946,78.499 29.946,126.746 39.369,136.169 213.029,136.169 213.029,154.711 208.863,158.877 31.012,158.877 1.32,129.184 1.32,75.235
12V_PRI on Layer 3 "LAYER_3_12V_PRI_P921" (solid, remove dead copper, pour order 921): 63 vertices, not listed, extent 1.218,1.245 217.932,135.763
DCLINK on Layer 3 "LAYER_3_DCLINK_P873" (solid, remove dead copper, pour order 873): 24 vertices, not listed, extent 38.242,33.045 92.633,128.013
IPRI_SENSE on Layer 3 "LAYER_3_IPRI_SENSE_P871" (solid, remove dead copper, pour order 871): 12.22,48.87 17.924,48.87 20.182,51.127 20.182,54.633 20.995,55.445 26.989,55.445 28.031,54.404 28.031,34.313 26.862,33.144 12.689,33.144 10.922,34.911 10.922,47.593
SW_C_RES on Layer 3 "NONET_L-01_P-001" (solid, remove dead copper, pour order 727): 169.061,108.134 168.379,108.817 161.686,108.817 161.025,108.157 161.025,104.677 161.686,104.017 168.388,104.017 169.061,104.663
SW_C_XFMR on Layer 3 "NONET_L-01_P-001" (solid, remove dead copper, pour order 725): 154.955,87.146 156.216,85.951 165.851,85.951 166.994,87.094 166.994,92.88 165.31,94.564 157.498,94.564 154.955,92.021
SW_C on Layer 3 "NONET_L-01_P-001" (solid, remove dead copper, pour order 723): 167.688,113.341 167.434,113.596 161.033,113.595 160.805,113.367 160.804,111.82 160.933,111.69 167.41,111.69 167.688,111.968
SW_D_RES on Layer 3 "NONET_L-01_P-001" (solid, remove dead copper, pour order 719): 155.056,64.691 156.428,63.319 170.169,63.319 170.703,63.853 170.703,72.463 169.458,73.708 156.199,73.708 155.056,72.51
VBATT on Layer 3 "LAYER_3_VBATT_P713" (solid, remove dead copper, pour order 713): 217.87,107.464 217.058,106.652 217.058,91.716 223.128,85.646 239.003,85.646 239.333,85.976 239.333,106.093 237.962,107.464
VBATT_F on Layer 3 "LAYER_3_VBATT_F_P711" (solid, remove dead copper, pour order 711): 209.488,106.632 209.488,93.342 210.555,92.275 215.254,92.275 216.346,93.367 216.346,106.652 215.356,107.642 210.364,107.642
BATT_RTN on Layer 3 "LAYER_3_BATT_RTN_P709" (solid, remove dead copper, pour order 709): 217.972,48.409 217.032,49.349 217.032,69.339 218.632,70.939 238.444,70.939 239.384,69.999 239.384,49.425 238.368,48.409
SGND on Layer 3 "LAYER_3_SGND_P705" (solid, remove dead copper, pour order 705): 162.549,37.513 163.286,38.249 170.042,38.249 171.083,37.208 171.083,33.144 170.525,32.585 163.286,32.585 162.549,33.322
SW_A_XFMR on Layer 3 "NONET_L-01_P-001" (solid, remove dead copper, pour order 511): 88.051,96.136 85.715,96.136 82.484,99.413 78.341,99.413 77.231,98.323 77.231,90.7 78.12,89.811 83.165,89.811 88.5,89.811 89.194,90.541 89.194,94.993
SGND on Layer 4 "LAYER_4_SGND_P1127" (solid, remove dead copper, pour order 1127): 31 vertices, not listed, extent 119.141,0.889 239.13,132.483
VBATT_F on Layer 4 "LAYER_4_VBATT_F_P1105" (solid, remove dead copper, pour order 1105): 188.341,32.69 187.579,33.452 187.579,35.992 188.163,36.576 196.377,36.576 196.85,36.103 196.85,33.37 196.17,32.69
SW_D on Layer 4 "LAYER_4_SW_D_P1097" (solid, remove dead copper, pour order 1097): 162.027,51.816 167.776,46.076 181.407,46.076 181.407,46.66 170.612,57.455 170.612,61.087 170.005,61.694 161.998,61.694 161.314,61.01 161.314,52.528
SGND on Layer 4 "LAYER_4_SGND_P1069" (solid, remove dead copper, pour order 1069): 214.782,156.007 217.551,158.775 238.404,158.775 239.37,157.81 239.37,110.084 237.973,108.687 208.458,108.687 204.343,112.801 204.343,114.046 204.775,114.478 217.957,114.478 220.345,116.865 220.345,131.699 214.782,137.262
PGND on Layer 4 "LAYER_4_PGND_P1049" (solid, remove dead copper, pour order 1049): 77 vertices, not listed, extent 0.75,1.143 217.957,159.258
SW_B on Layer 4 "LAYER_4_SW_B_P1011" (solid, remove dead copper, pour order 1011): 70.627,46.911 70.627,55.108 73.075,57.556 83.108,57.556 83.844,56.82 83.844,51.747 79.161,47.063 79.161,33.144 78.602,32.585 71.363,32.585 70.627,33.322
SW_B_RES on Layer 4 "LAYER_4_SW_B_RES_P1009" (solid, remove dead copper, pour order 1009): 73.113,59.118 73.113,63.335 79.803,70.025 88.711,70.025 89.321,69.415 89.321,63.592 84.2,58.471 73.761,58.471
DCLINK on Layer 4 "LAYER_4_DCLINK_P999" (solid, remove dead copper, pour order 999): 91.608,34.414 91.608,35.759 90.515,36.851 83.353,36.851 82.489,35.987 82.489,33.896 83.649,32.736 89.85,32.736
SW_A on Layer 4 "LAYER_4_SW_A_P997" (solid, remove dead copper, pour order 997): 65.641,125.096 65.641,126.441 64.549,127.533 57.386,127.533 56.522,126.67 56.523,124.579 57.682,123.419 63.884,123.419
SW_A on Layer 4 "LAYER_4_SW_A_P995" (solid, remove dead copper, pour order 995): 71.805,113.69 73.786,115.672 74.498,115.672 74.954,115.189 74.954,108.458 74.446,107.95 72.076,107.95 71.805,108.234
PGND on Layer 4 "LAYER_4_PGND_P977" (solid, remove dead copper, pour order 977): 34 vertices, not listed, extent 29.504,32.334 80.314,127.762
VBATT_F on Layer 4 "LAYER_4_VBATT_F_P967" (solid, remove dead copper, pour order 967): 42 vertices, not listed, extent 155.709,45.908 216.382,128.106
SW_C on Layer 4 "NONET_L-01_P-001" (solid, remove dead copper, pour order 951): 167.688,113.341 167.434,113.596 161.033,113.595 160.805,113.367 160.804,111.82 160.933,111.69 167.41,111.69 167.688,111.968
SW_C_RES on Layer 4 "NONET_L-01_P-001" (solid, remove dead copper, pour order 949): 169.061,108.134 168.379,108.817 161.686,108.817 161.025,108.157 161.025,104.677 161.943,103.759 168.12,103.759 169.061,104.663
DCLINK on Layer 4 "LAYER_4_DCLINK_P877" (solid, remove dead copper, pour order 877): 19 vertices, not listed, extent 38.242,58.188 53.405,128.013
IPRI_SENSE on Layer 4 "LAYER_4_IPRI_SENSE_P875" (solid, remove dead copper, pour order 875): 12.221,48.87 17.924,48.87 20.182,51.127 20.182,54.633 20.995,55.445 26.989,55.445 28.031,54.404 28.031,34.313 26.862,33.144 12.689,33.144 10.922,34.911 10.922,47.593
SW_C_XFMR on Layer 4 "NONET_L-01_P-001" (solid, remove dead copper, pour order 749): 154.955,87.146 156.216,85.951 165.851,85.951 166.994,87.094 166.994,92.88 165.31,94.564 157.498,94.564 154.955,92.021
SW_D on Layer 4 "NONET_L-01_P-001" (solid, remove dead copper, pour order 745): 183.439,36.601 184.342,35.698 184.342,35.059 184.342,33.517 183.49,32.664 175.463,32.664 174.538,33.59 174.538,35.763 175.376,36.601
SW_D_RES on Layer 4 "NONET_L-01_P-001" (solid, remove dead copper, pour order 743): 155.056,64.691 156.428,63.319 170.169,63.319 170.703,63.853 170.703,72.463 169.458,73.708 156.199,73.708 155.056,72.51
VBATT on Layer 4 "LAYER_4_VBATT_P737" (solid, remove dead copper, pour order 737): 217.87,107.464 217.058,106.652 217.058,91.716 223.128,85.646 239.003,85.646 239.333,85.976 239.333,106.093 237.962,107.464
VBATT_F on Layer 4 "LAYER_4_VBATT_F_P735" (solid, remove dead copper, pour order 735): 209.488,106.632 209.488,93.342 210.555,92.275 215.254,92.275 216.346,93.367 216.346,106.652 215.356,107.642 210.364,107.642
BATT_RTN on Layer 4 "LAYER_4_BATT_RTN_P733" (solid, remove dead copper, pour order 733): 218.823,48.409 217.398,49.835 217.398,69.704 218.632,70.939 238.444,70.939 239.384,69.999 239.384,49.425 238.368,48.409
VBATT_F on Layer 4 "LAYER_4_VBATT_F_P731" (solid, remove dead copper, pour order 731): 156.386,128.106 163.491,128.106 164.243,127.354 164.243,123.281 163.057,122.095 157.063,122.095 155.709,123.449 155.709,127.429
SGND on Layer 4 "LAYER_4_SGND_P729" (solid, remove dead copper, pour order 729): 162.549,37.513 163.286,38.249 170.042,38.249 171.083,37.208 171.083,33.144 170.525,32.585 163.286,32.585 162.549,33.322
SW_A_RES on Layer 4 "LAYER_4_SW_A_RES_P535" (solid, remove dead copper, pour order 535): 78.118,105.306 77.048,106.375 77.048,116.123 78.042,117.117 81.892,117.117 82.994,116.015 82.994,106.708 81.592,105.306
SW_A_XFMR on Layer 4 "NONET_L-01_P-001" (solid, remove dead copper, pour order 515): 88.051,96.136 85.715,96.136 82.484,99.413 78.341,99.413 77.231,98.323 77.231,90.7 78.12,89.811 83.165,89.811 88.5,89.811 89.194,90.541 89.194,94.993
SGND on Layer 5 "LAYER_5_SGND_P1125" (solid, remove dead copper, pour order 1125): 35 vertices, not listed, extent 119.141,0.711 239.13,158.95
PGND on Layer 5 "LAYER_5_PGND_P1121" (solid, remove dead copper, pour order 1121): 29 vertices, not listed, extent 0.888,0.735 217.957,159.029
IPRI_SENSE on Layer 5 "LAYER_5_IPRI_SENSE_P1119" (solid, remove dead copper, pour order 1119): 10.922,35.001 10.922,47.582 12.235,48.895 18.085,48.895 20.168,50.978 20.168,54.618 21.022,55.473 26.962,55.473 27.991,54.444 27.991,34.341 26.794,33.144 12.779,33.144
SW_A on Layer 5 "LAYER_5_SW_A_P1089" (solid, remove dead copper, pour order 1089): 72.136,108.102 74.221,108.102 74.549,108.431 74.549,115.265 74.32,115.494 73.787,115.494 72.009,113.716 72.009,108.229
DCLINK on Layer 5 "LAYER_5_DCLINK_P881" (solid, remove dead copper, pour order 881): 21 vertices, not listed, extent 38.242,58.188 53.405,128.013
SW_C_RES on Layer 5 "NONET_L-01_P-001" (solid, remove dead copper, pour order 799): 169.139,104.544 169.139,108.165 168.411,108.912 161.254,108.912 160.883,108.541 160.883,104.82 162.121,103.581 168.136,103.581
SW_C_XFMR on Layer 5 "NONET_L-01_P-001" (solid, remove dead copper, pour order 797): 154.955,87.146 156.216,85.951 165.851,85.951 166.994,87.094 166.994,92.975 165.532,94.437 157.371,94.437 154.955,92.021
SW_C on Layer 5 "NONET_L-01_P-001" (solid, remove dead copper, pour order 795): 160.781,114.655 160.781,111.304 161.188,110.896 169.342,110.896 177.51,119.064 177.51,126.845 176.9,127.454 169.001,127.454 167.731,126.184 167.731,121.604
SW_D on Layer 5 "NONET_L-01_P-001" (solid, remove dead copper, pour order 793): 169.941,61.719 170.601,61.059 170.601,60.284 170.601,57.503 184.342,43.761 184.342,32.89 183.453,32.001 175.402,32.001 174.538,32.865 174.538,39.265 161.355,52.448 161.355,55.741 161.355,61.099 162.008,61.719
SW_D_RES on Layer 5 "NONET_L-01_P-001" (solid, remove dead copper, pour order 791): 155.056,64.691 156.428,63.319 170.169,63.319 170.703,63.853 170.703,72.463 169.458,73.708 156.199,73.708 155.056,72.51
VBATT_F on Layer 5 "LAYER_5_VBATT_F_P789" (solid, remove dead copper, pour order 789): 20 vertices, not listed, extent 175.554,32.103 197.754,109.231
VBATT on Layer 5 "LAYER_5_VBATT_P785" (solid, remove dead copper, pour order 785): 217.87,107.464 217.058,106.652 217.058,91.716 223.128,85.646 239.003,85.646 239.333,85.976 239.333,106.093 237.962,107.464
VBATT_F on Layer 5 "LAYER_5_VBATT_F_P783" (solid, remove dead copper, pour order 783): 209.488,106.632 209.488,93.342 210.555,92.275 215.254,92.275 216.346,93.367 216.346,106.652 215.356,107.642 210.364,107.642
BATT_RTN on Layer 5 "LAYER_5_BATT_RTN_P781" (solid, remove dead copper, pour order 781): 217.972,48.409 217.032,49.349 217.032,69.339 218.632,70.939 238.444,70.939 239.384,69.999 239.384,49.425 238.368,48.409
VBATT_F on Layer 5 "LAYER_5_VBATT_F_P779" (solid, remove dead copper, pour order 779): 156.386,128.106 163.491,128.106 164.243,127.354 164.243,123.281 163.057,122.095 157.063,122.095 155.709,123.449 155.709,127.429
SGND on Layer 5 "LAYER_5_SGND_P777" (solid, remove dead copper, pour order 777): 162.549,37.513 163.286,38.249 170.042,38.249 171.083,37.208 171.083,33.144 170.525,32.585 163.286,32.585 162.549,33.322
SW_B on Layer 5 "LAYER_5_SW_B_P613" (solid, remove dead copper, pour order 613): 70.627,46.911 70.627,55.108 73.075,57.556 82.981,57.556 83.819,56.718 83.819,51.721 79.161,47.063 79.161,33.677 78.374,32.89 71.465,32.89 70.627,33.728
SW_B_RES on Layer 5 "LAYER_5_SW_B_RES_P611" (solid, remove dead copper, pour order 611): 73.74,58.466 84.093,58.466 89.321,63.693 89.321,69.415 88.711,70.025 79.739,70.025 73.1,63.386 73.1,59.106
SW_A_RES on Layer 5 "LAYER_5_SW_A_RES_P539" (solid, remove dead copper, pour order 539): 77.139,106.607 78.348,105.398 81.269,105.398 83.073,107.201 83.073,115.964 81.828,117.209 78.349,117.209 77.139,115.998
SW_A_XFMR on Layer 5 "NONET_L-01_P-001" (solid, remove dead copper, pour order 519): 88.051,96.136 85.715,96.136 82.484,99.413 78.341,99.413 77.231,98.323 77.231,90.7 78.12,89.811 83.165,89.811 88.5,89.811 89.194,90.541 89.194,94.993
SGND on Layer 2 "LAYER_2_SGND_P1077" (solid, remove dead copper, pour order 1077): 33 vertices, not listed, extent 119.141,0.889 239.13,132.483
SGND on Layer 2 "LAYER_2_SGND_P1073" (solid, remove dead copper, pour order 1073): 204.038,113.814 204.038,112.928 208.356,108.61 238.252,108.61 239.522,109.88 239.497,109.906 239.497,158.166 238.455,159.207 218.071,159.207 214.543,155.679 214.543,137.095 220.345,131.293 220.345,117.475 217.5,114.63 204.854,114.63
PGND on Layer 2 "LAYER_2_PGND_P1037" (solid, remove dead copper, pour order 1037): 70.06,126.67 70.949,127.559 78.061,127.559 78.595,127.025 78.595,123.826 78.036,123.268 70.797,123.268 70.06,124.004
PGND on Layer 2 "LAYER_2_PGND_P1035" (solid, remove dead copper, pour order 1035): 26 vertices, not listed, extent 29.504,32.588 66.563,111.582
SW_B on Layer 2 "LAYER_2_SW_B_P1021" (solid, remove dead copper, pour order 1021): 70.627,46.911 70.627,55.108 73.075,57.556 83.108,57.556 83.844,56.82 83.844,51.739 79.161,47.055 79.161,33.144 78.602,32.585 71.363,32.585 70.627,33.322
SW_B_RES on Layer 2 "LAYER_2_SW_B_RES_P1019" (solid, remove dead copper, pour order 1019): 73.113,59.118 73.113,63.335 79.803,70.025 88.711,70.025 89.321,69.415 89.321,63.592 84.2,58.471 73.761,58.471
SW_A_RES on Layer 2 "LAYER_2_SW_A_RES_P985" (solid, remove dead copper, pour order 985): 76.936,106.375 77.913,105.398 81.269,105.398 83.073,107.201 83.073,115.964 82.324,116.713 77.377,116.713 76.936,116.272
